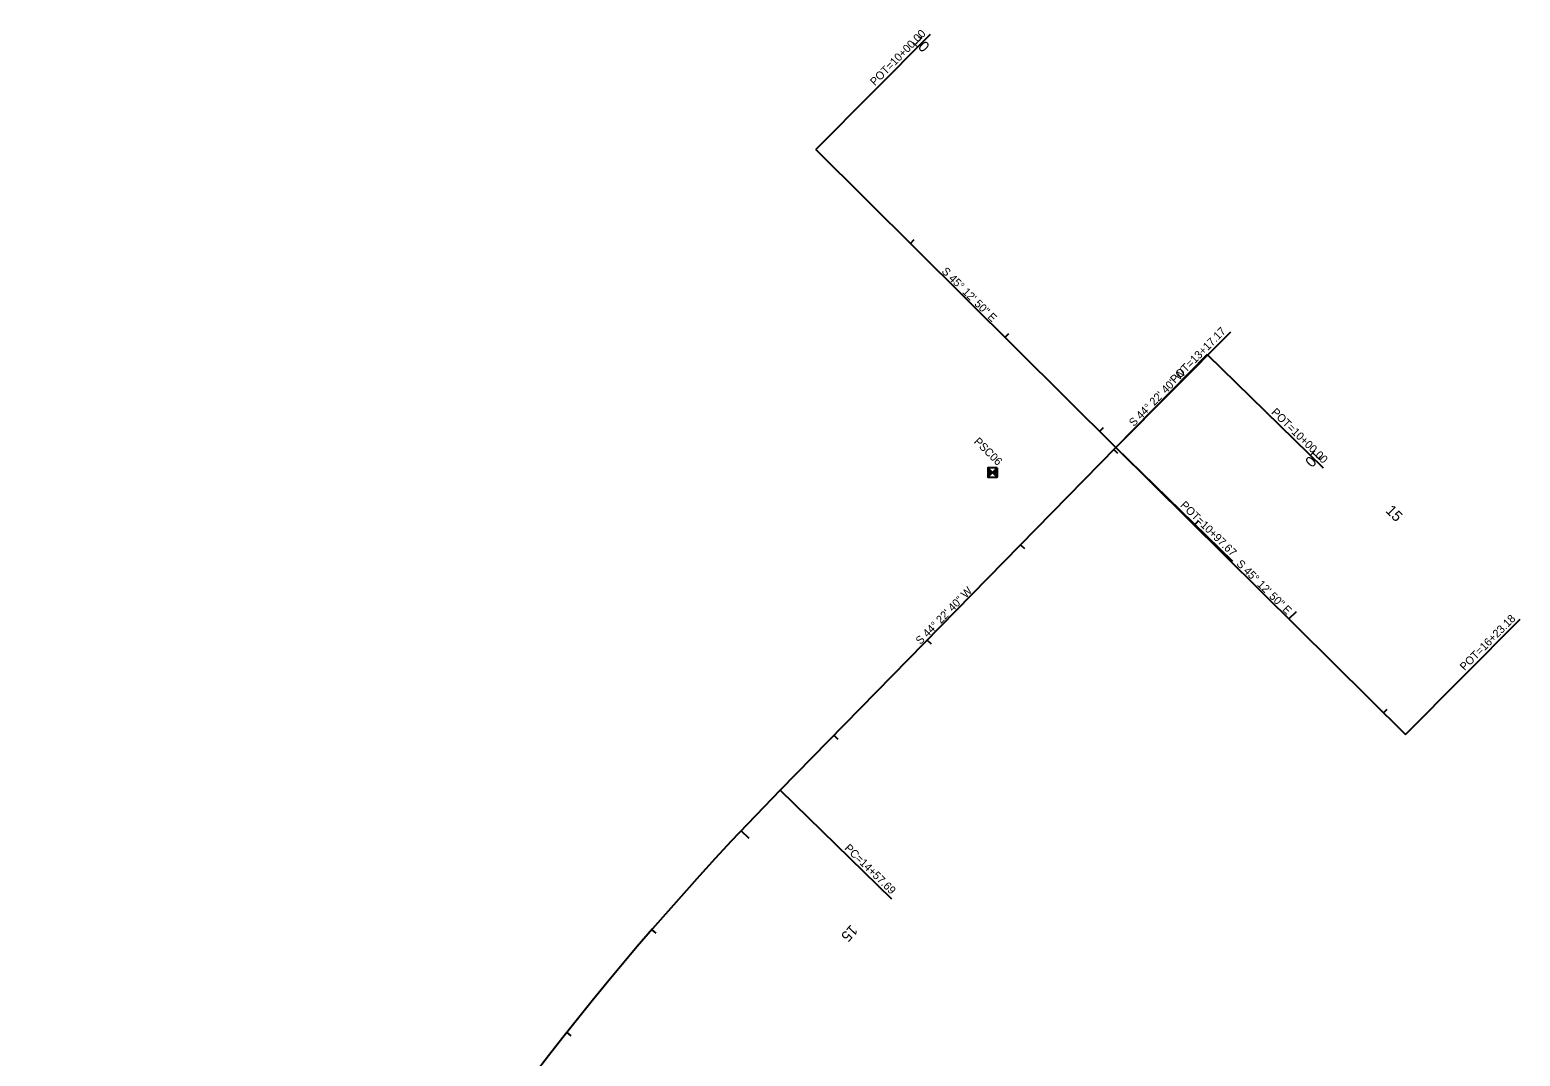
# Model space of a CAD drawing. Extents: x 2004390 to 2008791, y 1133870 to 1140084.
# Drawn here: x 2007673 to 2008791, y 1139314 to 1140084 of the extents above; entities that cross this region are included whole.
import ezdxf

# ---------------------------------------------------------------- set-up
doc = ezdxf.new("R2010")
doc.units = 0
for name, color, linetype in [('RD_HC_Cl', 7, 'Continuous'), ('RD_HC_Data', 7, 'Continuous'), ('RD_HC_Data_Tic', 7, 'Continuous'), ('RD_HC_Survey', 7, 'Continuous'), ('RD_HC_Survey_txCode', 7, 'Continuous'), ('RD_HC_TX_Sta50', 7, 'Continuous')]:
    doc.layers.add(name, color=color, linetype=linetype)

msp = doc.modelspace()

# ---------------------------------------------------------------- linework, layer by layer
at = {"layer": 'RD_HC_Cl'}
for p, q in [((2008262.5, 1139994.2), (2008487.6, 1139770.7)), ((2008555.9, 1139840.5), (2008487.6, 1139770.7)), ((2008487.6, 1139770.7), (2008235.8, 1139513.4)), ((2008487.6, 1139770.7), (2008704.8, 1139555.2))]:
    msp.add_line(p, q, dxfattribs=at)
msp.add_arc((2009874, 1137910.4), 2292, 135.6222, 163.7915, dxfattribs=at)
at = {"layer": 'RD_HC_Data'}
for p, q in [((2008262.5, 1139994.2), (2008348.5, 1140080.8)), ((2008487.6, 1139770.7), (2008573.7, 1139857.5)), ((2008555.9, 1139840.5), (2008643.1, 1139755.2)), ((2008487.6, 1139770.7), (2008575, 1139685.2)), ((2008704.8, 1139555.2), (2008790.8, 1139641.8)), ((2008235.8, 1139513.4), (2008319.2, 1139431.8))]:
    msp.add_line(p, q, dxfattribs=at)
at = {"layer": 'RD_HC_Data_Tic'}
for p, q in [((2008262.5, 1139994.2), (2008268.1, 1139999.8)), ((2008333.4, 1139923.7), (2008336.2, 1139926.6)), ((2008404.4, 1139853.3), (2008407.2, 1139856.1)), ((2008555.9, 1139840.5), (2008561.6, 1139834.9)), ((2008475.4, 1139782.8), (2008478.2, 1139785.7)), ((2008485.9, 1139769.1), (2008488.8, 1139766.3)), ((2008546.3, 1139712.4), (2008549.2, 1139715.2)), ((2008416, 1139697.6), (2008418.9, 1139694.8)), ((2008617.3, 1139641.9), (2008623, 1139647.6)), ((2008346.1, 1139626.1), (2008348.9, 1139623.3)), ((2008688.3, 1139571.5), (2008691.1, 1139574.3)), ((2008276.1, 1139554.6), (2008279, 1139551.8)), ((2008206.5, 1139482.9), (2008212.3, 1139477.4)), ((2008139.5, 1139408.7), (2008142.5, 1139406.1)), ((2008075.8, 1139331.6), (2008078.9, 1139329.1))]:
    msp.add_line(p, q, dxfattribs=at)
at = {"layer": 'RD_HC_Survey'}
for p, q in [((2008391.4, 1139755.3), (2008398.5, 1139748.3)), ((2008398.5, 1139755.3), (2008391.4, 1139748.3)), ((2008391.5, 1139755.3), (2008391.5, 1139748.3)), ((2008391.5, 1139755.2), (2008391.5, 1139748.4)), ((2008391.6, 1139755.2), (2008391.6, 1139748.4)), ((2008391.6, 1139755.1), (2008391.6, 1139748.5)), ((2008391.7, 1139755.1), (2008391.7, 1139748.5)), ((2008391.7, 1139755), (2008391.7, 1139748.6)), ((2008391.8, 1139755), (2008391.8, 1139748.6)), ((2008391.8, 1139754.9), (2008391.8, 1139748.7)), ((2008391.9, 1139754.9), (2008391.9, 1139748.7)), ((2008391.9, 1139754.8), (2008391.9, 1139748.8)), ((2008392, 1139754.8), (2008392, 1139748.8)), ((2008392, 1139754.7), (2008392, 1139748.9)), ((2008392.1, 1139754.7), (2008392.1, 1139748.9)), ((2008392.1, 1139754.6), (2008392.1, 1139749)), ((2008392.2, 1139754.6), (2008392.2, 1139749)), ((2008392.2, 1139754.5), (2008392.2, 1139749.1)), ((2008392.3, 1139754.5), (2008392.3, 1139749.1)), ((2008392.3, 1139754.4), (2008392.3, 1139749.2)), ((2008392.4, 1139754.4), (2008392.4, 1139749.2)), ((2008392.4, 1139754.3), (2008392.4, 1139749.3)), ((2008392.5, 1139754.3), (2008392.5, 1139749.3)), ((2008392.5, 1139754.2), (2008392.5, 1139749.4)), ((2008392.6, 1139754.2), (2008392.6, 1139749.4)), ((2008392.6, 1139754.1), (2008392.6, 1139749.5)), ((2008392.7, 1139754.1), (2008392.7, 1139749.5)), ((2008392.7, 1139754), (2008392.7, 1139749.6)), ((2008392.8, 1139754), (2008392.8, 1139749.6)), ((2008392.8, 1139753.9), (2008392.8, 1139749.7)), ((2008392.9, 1139753.9), (2008392.9, 1139749.7)), ((2008392.9, 1139753.8), (2008392.9, 1139749.8)), ((2008393, 1139753.8), (2008393, 1139749.8)), ((2008393, 1139753.7), (2008393, 1139749.9)), ((2008393.1, 1139753.7), (2008393.1, 1139749.9)), ((2008393.1, 1139753.6), (2008393.1, 1139750)), ((2008393.2, 1139753.6), (2008393.2, 1139750)), ((2008393.2, 1139753.5), (2008393.2, 1139750.1)), ((2008393.3, 1139753.5), (2008393.3, 1139750.1)), ((2008393.3, 1139753.4), (2008393.3, 1139750.2)), ((2008393.4, 1139753.4), (2008393.4, 1139750.2)), ((2008393.4, 1139753.3), (2008393.4, 1139750.3)), ((2008393.5, 1139753.3), (2008393.5, 1139750.3)), ((2008393.5, 1139753.2), (2008393.5, 1139750.4)), ((2008393.6, 1139753.2), (2008393.6, 1139750.4)), ((2008393.6, 1139753.1), (2008393.6, 1139750.5)), ((2008393.7, 1139753.1), (2008393.7, 1139750.5)), ((2008393.7, 1139753), (2008393.7, 1139750.6)), ((2008393.8, 1139753), (2008393.8, 1139750.6)), ((2008393.8, 1139752.9), (2008393.8, 1139750.7)), ((2008393.9, 1139752.9), (2008393.9, 1139750.7)), ((2008393.9, 1139752.8), (2008393.9, 1139750.8)), ((2008394, 1139752.8), (2008394, 1139750.8)), ((2008394, 1139752.7), (2008394, 1139750.9)), ((2008394.1, 1139752.7), (2008394.1, 1139750.9)), ((2008394.1, 1139752.6), (2008394.1, 1139751)), ((2008394.2, 1139752.6), (2008394.2, 1139751)), ((2008394.2, 1139752.5), (2008394.2, 1139751.1)), ((2008394.3, 1139752.5), (2008394.3, 1139751.1)), ((2008395.7, 1139752.5), (2008395.7, 1139751.1)), ((2008395.7, 1139752.5), (2008395.7, 1139751.1)), ((2008395.8, 1139752.6), (2008395.8, 1139751)), ((2008395.8, 1139752.6), (2008395.8, 1139751)), ((2008395.9, 1139752.7), (2008395.9, 1139750.9)), ((2008395.9, 1139752.7), (2008395.9, 1139750.9)), ((2008396, 1139752.8), (2008396, 1139750.8)), ((2008396, 1139752.8), (2008396, 1139750.8)), ((2008396.1, 1139752.9), (2008396.1, 1139750.7)), ((2008396.1, 1139752.9), (2008396.1, 1139750.7)), ((2008396.2, 1139753), (2008396.2, 1139750.6)), ((2008396.2, 1139753), (2008396.2, 1139750.6)), ((2008396.3, 1139753.1), (2008396.3, 1139750.5)), ((2008396.3, 1139753.1), (2008396.3, 1139750.5)), ((2008396.4, 1139753.2), (2008396.4, 1139750.4)), ((2008396.4, 1139753.2), (2008396.4, 1139750.4)), ((2008396.5, 1139753.3), (2008396.5, 1139750.3)), ((2008396.5, 1139753.3), (2008396.5, 1139750.3)), ((2008396.6, 1139753.4), (2008396.6, 1139750.2)), ((2008396.6, 1139753.4), (2008396.6, 1139750.2)), ((2008396.7, 1139753.5), (2008396.7, 1139750.1)), ((2008396.7, 1139753.5), (2008396.7, 1139750.1)), ((2008396.8, 1139753.6), (2008396.8, 1139750)), ((2008396.8, 1139753.6), (2008396.8, 1139750)), ((2008396.9, 1139753.7), (2008396.9, 1139749.9)), ((2008396.9, 1139753.7), (2008396.9, 1139749.9)), ((2008397, 1139753.8), (2008397, 1139749.8)), ((2008397, 1139753.8), (2008397, 1139749.8)), ((2008397.1, 1139753.9), (2008397.1, 1139749.7)), ((2008397.1, 1139753.9), (2008397.1, 1139749.7)), ((2008397.2, 1139754), (2008397.2, 1139749.6)), ((2008397.2, 1139754), (2008397.2, 1139749.6)), ((2008397.3, 1139754.1), (2008397.3, 1139749.5)), ((2008397.3, 1139754.1), (2008397.3, 1139749.5)), ((2008397.4, 1139754.2), (2008397.4, 1139749.4)), ((2008397.4, 1139754.2), (2008397.4, 1139749.4)), ((2008397.5, 1139754.3), (2008397.5, 1139749.3)), ((2008397.5, 1139754.3), (2008397.5, 1139749.3)), ((2008397.6, 1139754.4), (2008397.6, 1139749.2)), ((2008397.6, 1139754.4), (2008397.6, 1139749.2)), ((2008397.7, 1139754.5), (2008397.7, 1139749.1)), ((2008397.7, 1139754.5), (2008397.7, 1139749.1)), ((2008397.8, 1139754.6), (2008397.8, 1139749)), ((2008397.8, 1139754.6), (2008397.8, 1139749)), ((2008397.9, 1139754.7), (2008397.9, 1139748.9)), ((2008397.9, 1139754.7), (2008397.9, 1139748.9)), ((2008398, 1139754.8), (2008398, 1139748.8)), ((2008398, 1139754.8), (2008398, 1139748.8)), ((2008398.1, 1139754.9), (2008398.1, 1139748.7)), ((2008398.1, 1139754.9), (2008398.1, 1139748.7)), ((2008398.2, 1139755), (2008398.2, 1139748.6)), ((2008398.2, 1139755), (2008398.2, 1139748.6)), ((2008398.3, 1139755.1), (2008398.3, 1139748.5)), ((2008398.3, 1139755.1), (2008398.3, 1139748.5)), ((2008398.4, 1139755.2), (2008398.4, 1139748.4)), ((2008398.4, 1139755.2), (2008398.4, 1139748.4)), ((2008398.5, 1139755.3), (2008398.5, 1139748.3)), ((2008394.3, 1139752.4), (2008394.3, 1139751.2)), ((2008394.4, 1139752.4), (2008394.4, 1139751.2)), ((2008394.4, 1139752.3), (2008394.4, 1139751.3)), ((2008394.5, 1139752.3), (2008394.5, 1139751.3)), ((2008394.5, 1139752.2), (2008394.5, 1139751.4)), ((2008394.6, 1139752.2), (2008394.6, 1139751.4)), ((2008394.6, 1139752.1), (2008394.6, 1139751.5)), ((2008394.7, 1139752.1), (2008394.7, 1139751.5)), ((2008394.7, 1139752), (2008394.7, 1139751.6)), ((2008394.8, 1139752), (2008394.8, 1139751.6)), ((2008394.8, 1139751.9), (2008394.8, 1139751.7)), ((2008394.9, 1139751.9), (2008394.9, 1139751.7)), ((2008394.9, 1139751.8), (2008394.9, 1139751.8)), ((2008395, 1139751.8), (2008395, 1139751.8)), ((2008395.1, 1139751.9), (2008395.1, 1139751.7)), ((2008395.1, 1139751.9), (2008395.1, 1139751.7)), ((2008395.2, 1139752), (2008395.2, 1139751.6)), ((2008395.2, 1139752), (2008395.2, 1139751.6)), ((2008395.3, 1139752.1), (2008395.3, 1139751.5)), ((2008395.3, 1139752.1), (2008395.3, 1139751.5)), ((2008395.4, 1139752.2), (2008395.4, 1139751.4)), ((2008395.4, 1139752.2), (2008395.4, 1139751.4)), ((2008395.5, 1139752.3), (2008395.5, 1139751.3)), ((2008395.5, 1139752.3), (2008395.5, 1139751.3)), ((2008395.6, 1139752.4), (2008395.6, 1139751.2)), ((2008395.6, 1139752.4), (2008395.6, 1139751.2))]:
    msp.add_line(p, q, dxfattribs=at)
msp.add_lwpolyline([(2008398.5, 1139755.3), (2008391.4, 1139755.3), (2008391.4, 1139748.3), (2008398.5, 1139748.3)], close=True, dxfattribs=at)

# ---------------------------------------------------------------- texts
at = {"layer": 'RD_HC_Data'}
for s, rotation, p in [('POT=10+00.00', 45.214, (2008306.8, 1140041.7)), ('S 45%%d 12\' 50" E', 315.214, (2008356.4, 1139902.3)), ('POT=13+17.17', 45.214, (2008531.9, 1139818.3)), ('S 44%%d 22\' 40" W', 45.6222, (2008501, 1139785.9)), ('POT=10+00.00', 315.6222, (2008603.7, 1139796.5)), ('POT=10+97.67', 315.6222, (2008535.4, 1139726.7)), ('S 45%%d 12\' 50" E', 315.214, (2008577.5, 1139682.8)), ('S 44%%d 22\' 40" W', 45.6222, (2008341, 1139622.3)), ('POT=16+23.18', 45.214, (2008749.1, 1139602.7)), ('PC=14+57.69', 315.6222, (2008283.6, 1139469.4))]:
    msp.add_text(s, height=6, rotation=rotation, dxfattribs=at).set_placement(p)
at = {"layer": 'RD_HC_Survey_txCode'}
msp.add_text('PSC06', height=6, rotation=315.214, dxfattribs=at).set_placement((2008380.7, 1139774.5))
at = {"layer": 'RD_HC_TX_Sta50'}
for s, rotation, p in [('10', 315.214, (2008334.4, 1140074.9)), ('10', 225.6222, (2008637.1, 1139769.1)), ('15', 315.214, (2008689.3, 1139722.6)), ('15', 226.6798, (2008289, 1139413))]:
    msp.add_text(s, height=8, rotation=rotation, dxfattribs=at).set_placement(p)

doc.saveas('drawing.dxf')
